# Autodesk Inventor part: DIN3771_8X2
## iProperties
Created: 2007-03
Part Number: DIN3771_8X2
Document SubType Name: Modeling
Designer: Andy Moles
Material: Rubber
Mass: 0.0917873 g
Surface Area: 1.97392 cm^2
Volume: 0.098696 cm^3
Density: 0.93 g/cm^3
Author: Andy Moles
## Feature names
1. Base1
